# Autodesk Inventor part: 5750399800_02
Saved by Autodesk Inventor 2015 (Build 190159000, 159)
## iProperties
Created: 2020-07
Part Number: 5750399800_02
Checked By: TraceParts S.A.
Material: Generic
Catalog Web Link: www.traceparts.com
Document SubType Name: Modeling
Designer: TraceParts
Density: 1 g/cm^3
Appearance: Default
Company: TraceParts S.A.
Author: TraceParts
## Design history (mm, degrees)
feature "5750399800_02.ipt"
body "Solid1"
